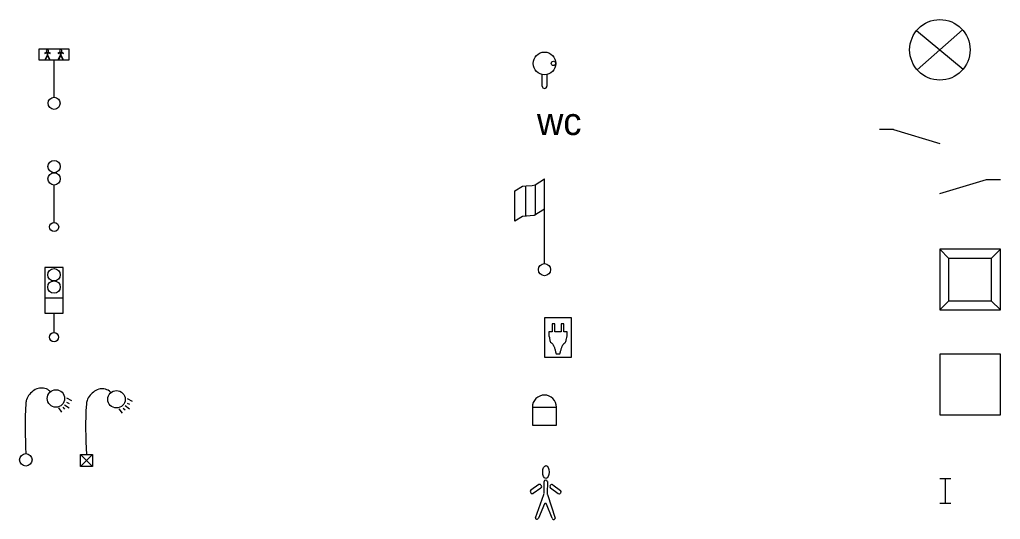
# Model space of a CAD drawing. Extents: x -1.5 to 18.2, y -66.6 to 3.3.
# Drawn here: x -0.41 to 15.81, y -51.87 to -43.61 of the extents above; entities that cross this region are included whole.
import ezdxf

# ---------------------------------------------------------------- set-up
doc = ezdxf.new("R2010")
doc.units = 0
for name, color, linetype in [('SOL_BORDURE', 7, 'Continuous'), ('SOL_CANDELABRE', 7, 'Continuous'), ('SOL_FEU_TRICOLORE_ET_PIETON', 7, 'Continuous'), ('SOL_FONTAINE', 7, 'Continuous'), ('SOL_LIMITE_REVETEMENT', 7, 'Continuous'), ('SOL_MOBILIER_DIVERS', 7, 'Continuous'), ('SOL_MUR', 7, 'Continuous'), ('SOL_POTEAU', 7, 'Continuous'), ('SOL_SIGNALISATION_HORIZONTALE', 7, 'Continuous'), ('SOL_TELECOM_POTEAU', 7, 'Continuous')]:
    doc.layers.add(name, color=color, linetype=linetype)

# ---------------------------------------------------------------- blocks, each defined once
blk = doc.blocks.new('FEU_PIETON')
for p, q in [((-0.116, 0.847), (-0.157, 0.828)), ((-0.154, 0.822), (-0.116, 0.84)), ((-0.116, 0.847), (-0.101, 0.847)), ((-0.116, 0.84), (-0.116, 0.798)), ((-0.101, 0.847), (-0.102, 0.847)), ((-0.061, 0.828), (-0.101, 0.847)), ((-0.101, 0.798), (-0.101, 0.84)), ((-0.101, 0.84), (-0.064, 0.822)), ((0.102, 0.847), (0.062, 0.828)), ((0.065, 0.822), (0.102, 0.84)), ((0.102, 0.847), (0.117, 0.847)), ((0.102, 0.84), (0.102, 0.798)), ((0.158, 0.828), (0.117, 0.847)), ((0.117, 0.847), (0.117, 0.847)), ((0.117, 0.798), (0.117, 0.84)), ((0.117, 0.84), (0.155, 0.822)), ((-0.116, 0.798), (-0.15, 0.726)), ((-0.142, 0.726), (-0.109, 0.785)), ((-0.109, 0.785), (-0.075, 0.726)), ((-0.068, 0.726), (-0.101, 0.798)), ((0, 0.098), (0, 0.715)), ((0.102, 0.798), (0.069, 0.726)), ((0.076, 0.726), (0.11, 0.785)), ((0.11, 0.785), (0.143, 0.726)), ((0.15, 0.726), (0.117, 0.798))]:
    blk.add_line(p, q)
blk.add_lwpolyline([(-0.247, 0.9), (0.246, 0.9), (0.246, 0.715), (-0.247, 0.715)], close=True)
blk.add_circle((0, 0), 0.1)
for centre in [(-0.109, 0.866), (0.11, 0.866)]:
    blk.add_arc(centre, 0.0198, 291.1041, 248.8959)
blk = doc.blocks.new('FEU_BICOLORE')
blk.add_lwpolyline([(0, 0.075), (0, 0.693)])
for centre, radius in [((0, 0.999), 0.102), ((0, 0.795), 0.102), ((0.001, 0.001), 0.075)]:
    blk.add_circle(centre, radius)
blk = doc.blocks.new('FEU_BICOLORE_BADGE')
blk.add_line((-0.151, 0.649), (0.151, 0.649))
blk.add_lwpolyline([(0, 0.075), (0, 0.398), (0.151, 0.398), (0.151, 1.15), (-0.151, 1.15), (-0.151, 0.398), (0.151, 0.398)])
for centre, radius in [((-0.001, 1.032), 0.102), ((-0.001, 0.829), 0.102), ((0, 0), 0.075)]:
    blk.add_circle(centre, radius)
blk = doc.blocks.new('CANDELABRE_SIMPLE')
for points in [[(0.673, 1.025), (0.756, 0.983)], [(0.539, 0.859), (0.59, 0.787)], [(0.611, 0.87), (0.642, 0.839)], [(0.642, 0.911), (0.715, 0.859)], [(0.673, 0.952), (0.715, 0.932)]]:
    blk.add_lwpolyline(points)
for centre, radius in [((0.4975, 1.0145), 0.1441), ((0.0005, 0.001), 0.1035)]:
    blk.add_circle(centre, radius)
blk.add_spline([(0.404, 1.128), (0.383, 1.149), (0.29, 1.185), (0.228, 1.185), (0.135, 1.149), (0.063, 1.082), (0.011, 0.994), (0.001, 0.932), (0.001, 0.104)], degree=3)
blk = doc.blocks.new('SYMBOLE_PIETON')
for points in [[(-0.025, -0.006), (-0.022, 0.187)], [(0.031, 0.187), (0.028, -0.007)], [(-0.25, 0.011), (-0.243, 0.001)], [(-0.112, 0.138), (-0.243, 0.048)], [(-0.206, -0.006), (-0.075, 0.083)], [(-0.068, 0.12), (-0.075, 0.131)], [(0.074, 0.118), (0.082, 0.129)], [(0.209, -0.012), (0.08, 0.081)], [(0.119, 0.135), (0.248, 0.042)], [(0.254, 0.005), (0.246, -0.006)], [(-0.168, -0.409), (-0.029, -0.027)], [(0.032, -0.028), (0.161, -0.414)], [(-0.015, -0.182), (-0.117, -0.415)], [(0.11, -0.418), (0.014, -0.183)]]:
    blk.add_lwpolyline(points)
for centre, radius, start, end in [((0.004, 0.187), 0.0265, 89.2382, 179.2382), ((0.004, 0.187), 0.0265, 359.2382, 89.2382), ((-0.228, 0.026), 0.0265, 124.2382, 214.2382), ((-0.221, 0.015), 0.0265, 214.2382, 304.2382), ((-0.097, 0.116), 0.0265, 34.2382, 124.2382), ((-0.089, 0.105), 0.0265, 304.2382, 34.2382), ((0.096, 0.102), 0.0265, 144.2382, 234.2382), ((0.103, 0.113), 0.0265, 54.2382, 144.2382), ((0.232, 0.02), 0.0265, 324.2382, 54.2382), ((-0.078, -0.006), 0.053, 336.3803, 359.2382), ((0.081, -0.008), 0.053, 179.2382, 202.096), ((0.225, 0.01), 0.0265, 234.2382, 324.2382), ((-0.001, -0.189), 0.0159, 22.1488, 156.3275), ((-0.142, -0.406), 0.0265, 187.6708, 278.5109), ((-0.142, -0.406), 0.0265, 278.5109, 339.838), ((0.135, -0.41), 0.0265, 198.6384, 259.9654), ((0.135, -0.41), 0.0265, 259.9654, 350.8056)]:
    blk.add_arc(centre, radius, start, end)
blk.add_ellipse((0.006, 0.346), major_axis=(-0.001, -0.106), ratio=0.5)
blk = doc.blocks.new('FONTAINE')
for p, q in [((-0.036, -0.376), (-0.036, -0.183)), ((0.039, -0.184), (0.04, -0.375))]:
    blk.add_line(p, q)
for centre, radius in [((0, 0), 0.187), ((0.149, 0), 0.0366)]:
    blk.add_circle(centre, radius)
blk.add_ellipse((0.002, -0.375), major_axis=(-0.0005, 0.0381), ratio=0.994702, start_param=1.586432, end_param=4.712389)
blk = doc.blocks.new('WC')
blk.add_text('wc', height=0.45).set_placement((-0.123, 0.075))
blk = doc.blocks.new('POTEAU_MAT')
for p, q in [((0, 0.1), (0, 1.5)), ((-0.315, 1.384), (-0.315, 0.884)), ((-0.156, 1.403), (-0.156, 0.903))]:
    blk.add_line(p, q)
blk.add_lwpolyline([(0, 1), (-0.169, 0.896), (-0.365, 0.881), (-0.49, 0.804), (-0.49, 1.304), (-0.365, 1.381), (-0.3, 1.386), (-0.202, 1.393), (-0.156, 1.403), (0, 1.5)])
blk.add_circle((0, 0), 0.1)
blk = doc.blocks.new('BORNE_RECHARGE_ELECTRIQUE')
for p, q in [((0.45, 0.65), (0, 0.65)), ((0, 0.65), (0, 0)), ((0.45, 0), (0.45, 0.65)), ((0, 0), (0.45, 0))]:
    blk.add_line(p, q)
for points in [[(0.375, 0.354), (0.375, 0.419), (0.322, 0.419), (0.322, 0.55), (0.279, 0.55), (0.279, 0.419), (0.171, 0.419), (0.171, 0.55), (0.128, 0.55), (0.128, 0.419)], [(0.128, 0.419), (0.075, 0.419), (0.075, 0.354)], [(0.193, 0.057), (0.257, 0.057)]]:
    blk.add_lwpolyline(points)
for points in [[(0.075, 0.354), (0.08, 0.328), (0.086, 0.303), (0.091, 0.277), (0.098, 0.247), (0.131, 0.228), (0.145, 0.201), (0.155, 0.18), (0.166, 0.16), (0.172, 0.137), (0.179, 0.111), (0.186, 0.084), (0.193, 0.057)], [(0.257, 0.057), (0.264, 0.084), (0.271, 0.111), (0.278, 0.137), (0.284, 0.16), (0.295, 0.18), (0.305, 0.201), (0.319, 0.228), (0.352, 0.247), (0.359, 0.277), (0.364, 0.303), (0.37, 0.328), (0.375, 0.354)]]:
    blk.add_open_spline(points, degree=3)
blk = doc.blocks.new('BORNE_KILOMETRIQUE')
for p, q in [((-0.2, 0.3), (0.2, 0.3)), ((-0.2, 0.3), (-0.2, 0)), ((0.2, 0), (0.2, 0.3)), ((-0.2, 0), (0.2, 0))]:
    blk.add_line(p, q)
blk.add_arc((0, 0.3), 0.2, 0, 180)
blk = doc.blocks.new('PILIER_MUR_ROND')
for p, q in [((0.374, 0.332), (-0.374, -0.332)), ((-0.385, 0.319), (0.385, -0.319))]:
    blk.add_line(p, q)
blk.add_circle((0, 0), 0.5)
blk = doc.blocks.new('CHARTIERE_GAUCHE')
for points in [[(-0.769, 0.23), (-0.999, 0.23)], [(-0.769, 0.23), (0.001, 0)]]:
    blk.add_lwpolyline(points)
blk = doc.blocks.new('CHARTIERE_DROITE')
blk.add_lwpolyline([(0, 0), (0.77, 0.23), (1, 0.23)])
blk = doc.blocks.new('RALENTISSEUR')
for p, q in [((0.15, 0.85), (0, 1)), ((0.85, 0.85), (1, 1)), ((0.15, 0.15), (0.15, 0.85)), ((0.85, 0.85), (0.15, 0.85)), ((0.85, 0.85), (0.85, 0.15)), ((0.15, 0.15), (0, 0)), ((0.15, 0.15), (0.85, 0.15)), ((0.85, 0.15), (1, 0))]:
    blk.add_line(p, q)
blk.add_lwpolyline([(0, 0), (1, 0), (1, 1), (0, 1)], close=True)
blk = doc.blocks.new('BANDE_PODOTACTILE')
blk.add_lwpolyline([(0, 0), (1, 0), (1, 1), (0, 1)], close=True)
blk = doc.blocks.new('IPN')
for p, q in [((0.18, 0.4), (0, 0.4)), ((0.09, 0), (0.09, 0.4)), ((0, 0), (0.18, 0))]:
    blk.add_line(p, q)
blk = doc.blocks.new('CANDELABRE_SIMPLE_BETON')
for p, q in [((-0.0995, -0.099), (0.1005, 0.101)), ((-0.0995, 0.101), (0.1005, -0.099))]:
    blk.add_line(p, q)
for points in [[(0.673, 1.025), (0.756, 0.983)], [(0.539, 0.859), (0.59, 0.787)], [(0.611, 0.87), (0.642, 0.839)], [(0.642, 0.911), (0.715, 0.859)], [(0.673, 0.952), (0.715, 0.932)]]:
    blk.add_lwpolyline(points)
blk.add_lwpolyline([(-0.0995, 0.101), (0.1005, 0.101), (0.1005, -0.099), (-0.0995, -0.099)], close=True)
blk.add_circle((0.4975, 1.0145), 0.1441)
blk.add_spline([(0.404, 1.128), (0.383, 1.149), (0.29, 1.185), (0.228, 1.185), (0.135, 1.149), (0.063, 1.082), (0.011, 0.994), (0.001, 0.932), (0.001, 0.104)], degree=3)

msp = doc.modelspace()

# ---------------------------------------------------------------- block references
at = {"layer": 'SOL_BORDURE'}
for name, p in [('CHARTIERE_GAUCHE', (14.805, -45.651)), ('CHARTIERE_DROITE', (14.805, -46.48))]:
    msp.add_blockref(name, p, dxfattribs=at)
at = {"layer": 'SOL_CANDELABRE'}
msp.add_blockref('CANDELABRE_SIMPLE', (-0.307, -50.883), dxfattribs=at)
at = {"layer": 'SOL_FEU_TRICOLORE_ET_PIETON'}
for name, p in [('FEU_PIETON', (0.16, -44.989)), ('FEU_BICOLORE', (0.16, -47.034)), ('FEU_BICOLORE_BADGE', (0.16, -48.855))]:
    msp.add_blockref(name, p, dxfattribs=at)
at = {"layer": 'SOL_FONTAINE'}
msp.add_blockref('FONTAINE', (8.267, -44.33), dxfattribs=at)
at = {"layer": 'SOL_LIMITE_REVETEMENT'}
for name, p in [('RALENTISSEUR', (14.805, -48.403)), ('BANDE_PODOTACTILE', (14.805, -50.136))]:
    msp.add_blockref(name, p, dxfattribs=at)
at = {"layer": 'SOL_MOBILIER_DIVERS'}
for name, p in [('WC', (8.267, -45.589)), ('BORNE_RECHARGE_ELECTRIQUE', (8.267, -49.186)), ('BORNE_KILOMETRIQUE', (8.267, -50.312))]:
    msp.add_blockref(name, p, dxfattribs=at)
at = {"layer": 'SOL_MUR'}
for name, p in [('PILIER_MUR_ROND', (14.805, -44.106)), ('IPN', (14.805, -51.599))]:
    msp.add_blockref(name, p, dxfattribs=at)
at = {"layer": 'SOL_POTEAU'}
msp.add_blockref('POTEAU_MAT', (8.267, -47.739), dxfattribs=at)
at = {"layer": 'SOL_SIGNALISATION_HORIZONTALE'}
msp.add_blockref('SYMBOLE_PIETON', (8.285, -51.43), dxfattribs=at)
at = {"layer": 'SOL_TELECOM_POTEAU'}
msp.add_blockref('CANDELABRE_SIMPLE_BETON', (0.694, -50.896), dxfattribs=at)

doc.saveas('drawing.dxf')
